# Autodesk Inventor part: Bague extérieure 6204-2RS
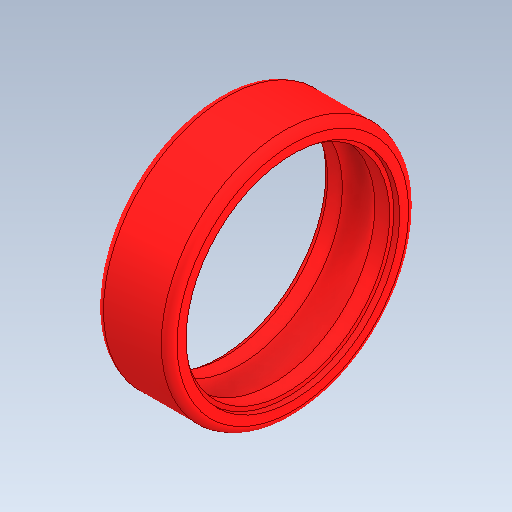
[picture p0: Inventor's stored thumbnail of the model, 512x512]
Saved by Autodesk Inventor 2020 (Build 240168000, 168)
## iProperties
Created: 2003-06
Part Number: Bague extérieure 6204-2RS
Material: Générique
Document SubType Name: Modeling
Designer: Bruno
Density: 1 g/cm^3
Appearance: Par défaut
Author: Bruno
Sending System: SolidWorks 2011
Last Author: frederic
Last Saved: 2012-02-20
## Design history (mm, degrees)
feature "Base-Révolution"
node "Solide1"
